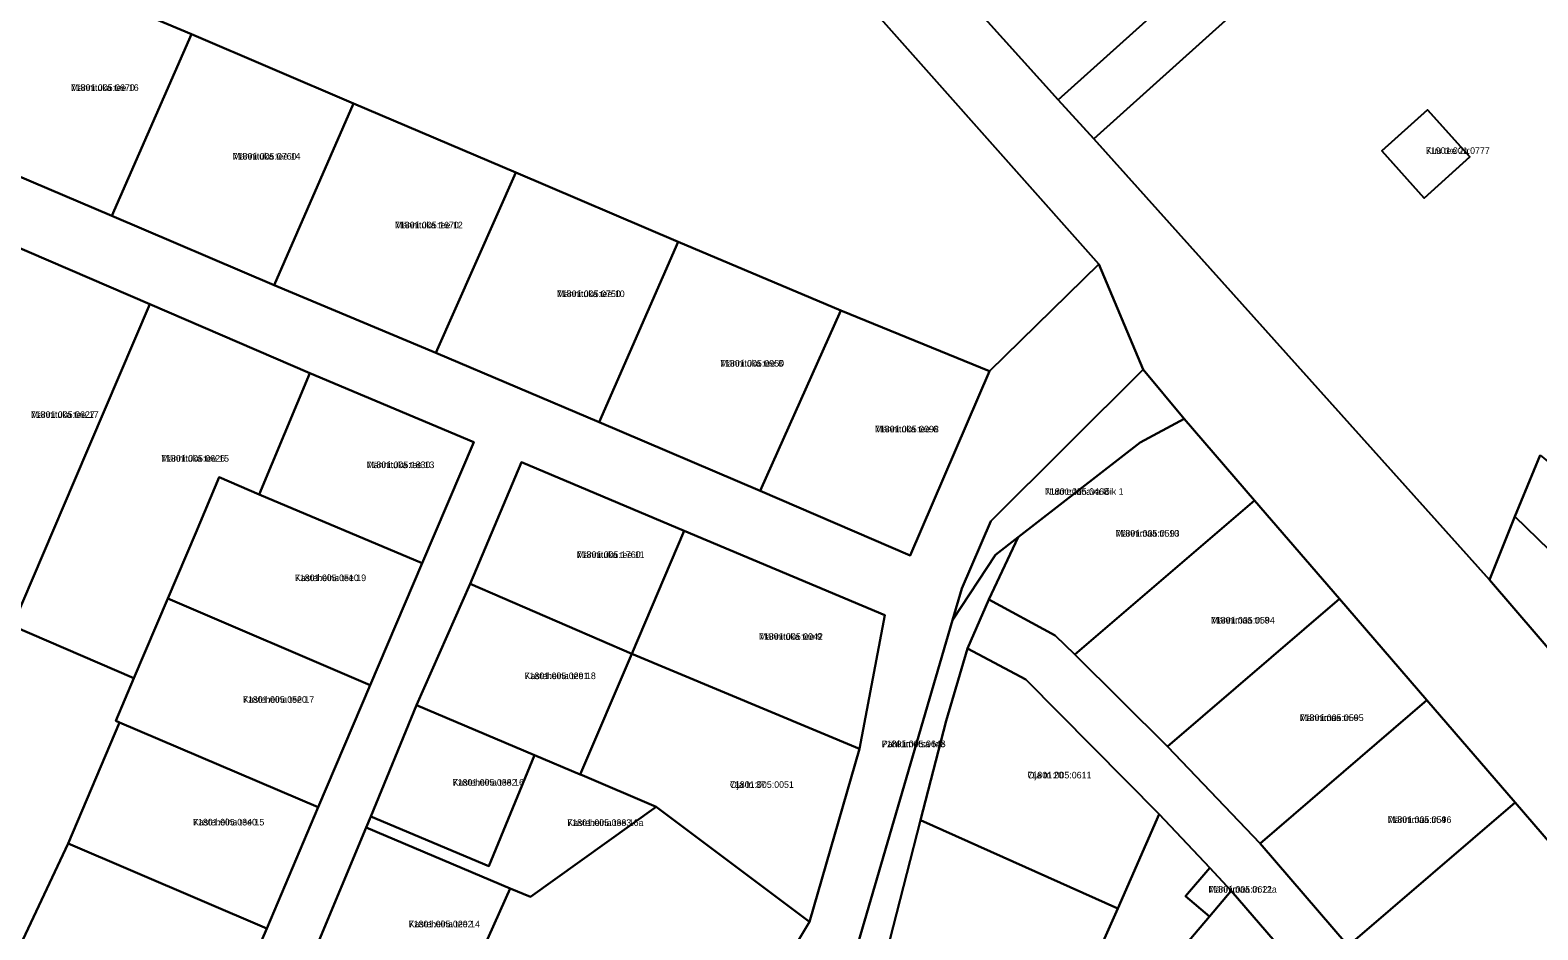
# Model space of a CAD drawing. Extents: x 529768 to 552006, y 6562269 to 6580975.
# Drawn here: x 536849.5 to 537191.7, y 6574356.4 to 6574560.6 of the extents above; entities that cross this region are included whole.
import ezdxf

# ---------------------------------------------------------------- set-up
doc = ezdxf.new("R2010")
doc.units = 0
for name, color, linetype in [('L_AADRESS', 7, 'Continuous'), ('PIIR', 7, 'Continuous'), ('TUNNUS', 7, 'Continuous')]:
    doc.layers.add(name, color=color, linetype=linetype)

msp = doc.modelspace()

# ---------------------------------------------------------------- linework, layer by layer
at = {"layer": 'PIIR'}
for points in [[(536590, 6574730.51), (536689.98, 6574754.28), (536735.05, 6574764.99), (536753.27, 6574769.32), (536801.83, 6574780.81), (536855.94, 6574790.6), (536939.88, 6574703.31), (536970.4, 6574669.45), (537007.93, 6574627.87), (537045.37, 6574586.35), (537082.85, 6574544.79), (537090.91, 6574535.89), (537180.73, 6574435.88), (537224.86, 6574384.41)], [(537192.18, 6574464.15), (537186.43, 6574450.25), (537180.73, 6574435.88), (537090.91, 6574535.89), (537128.25, 6574569.55), (537128.23, 6574583.36), (537176.67, 6574583.41), (537176.67, 6574608.16), (537176.65, 6574632.98), (537176.69, 6574663.91), (537176.66, 6574694.89), (537176.65, 6574725.87), (537176.64, 6574780.86), (537192.46, 6574780.83)], [(537204.91, 6574363.99), (537186.5, 6574385.35), (537166.46, 6574408.59), (537146.64, 6574431.57), (537127.41, 6574453.87), (537111.43, 6574472.43), (537102.12, 6574483.57), (537092.03, 6574507.49), (536928.63, 6574691.42), (536926.96, 6574690.25), (536887.33, 6574717.24), (536796.81, 6574745.22), (536713.32, 6574740.69), (536520.11, 6574695.44)], [(537128.25, 6574569.55), (537090.91, 6574535.89), (537082.85, 6574544.79), (537110.82, 6574569.97)], [(536831.37, 6574534.01), (536868.06, 6574518.43), (536904.91, 6574502.75), (536941.57, 6574487.39), (536978.69, 6574471.64), (537015.22, 6574456.04), (537049.26, 6574441.38), (537067.26, 6574483.19), (537092.03, 6574507.49), (537102.12, 6574483.57), (537067.51, 6574449.2), (537060.96, 6574433.92), (537058.85, 6574426.74), (537037.46, 6574353.46)], [(536848.11, 6574218.76), (536855.09, 6574238.97), (536868.03, 6574273.98), (536879.6, 6574301.9), (536891.37, 6574329.26), (536903.26, 6574356.78), (536914.89, 6574384.31), (536926.66, 6574411.99), (536938.46, 6574439.65), (536950.24, 6574467.12), (536913.03, 6574482.78), (536876.66, 6574498.44), (536839.93, 6574514.2)], [(537000.17, 6574314.62), (537026.37, 6574358.24), (537037.73, 6574397.52), (537043.52, 6574427.85), (536997.92, 6574446.98), (536961, 6574462.58), (536949.35, 6574434.97), (536937.24, 6574407.39), (536926.84, 6574382.16), (536925.81, 6574379.67), (536914.39, 6574352.3)], [(537037.46, 6574353.46), (537058.85, 6574426.74), (537068.61, 6574441.57), (537073.71, 6574445.54), (537067.08, 6574431.41), (537062.23, 6574420.29), (537057.44, 6574403.85), (537051.59, 6574381.3), (537042.29, 6574345.06)], [(537164.41, 6574316.2), (537122.1, 6574365.31), (537117.24, 6574370.49), (537105.74, 6574382.67), (537075.45, 6574413.25), (537062.23, 6574420.29), (537067.08, 6574431.41), (537082.18, 6574423.23), (537086.64, 6574418.89), (537107.65, 6574398.03), (537128.66, 6574376.07), (537148.66, 6574352.81)]]:
    msp.add_lwpolyline(points, dxfattribs=at)
for points in [[(536928.63, 6574691.42), (537092.03, 6574507.49), (537067.26, 6574483.19), (537033.54, 6574496.94), (536996.55, 6574512.59), (536959.71, 6574528.31), (536922.92, 6574543.94), (536886.16, 6574559.68), (536849.27, 6574575.22), (536820.53, 6574587.72), (536818.21, 6574611.88), (536926.96, 6574690.25)], [(537045.37, 6574586.35), (537078.53, 6574616.33), (537115.01, 6574576), (537113.2, 6574572.75), (537110.82, 6574569.97), (537082.85, 6574544.79)], [(536831.37, 6574534.01), (536849.27, 6574575.22), (536886.16, 6574559.68), (536868.06, 6574518.43)], [(536868.06, 6574518.43), (536886.16, 6574559.68), (536922.92, 6574543.94), (536904.91, 6574502.75)], [(536922.92, 6574543.94), (536959.71, 6574528.31), (536941.57, 6574487.39), (536904.91, 6574502.75)], [(537166.61, 6574542.53), (537156.28, 6574533.19), (537165.92, 6574522.49), (537176.26, 6574531.83)], [(537156.28, 6574533.19), (537166.61, 6574542.53), (537176.26, 6574531.83), (537165.92, 6574522.49)], [(536941.57, 6574487.39), (536959.71, 6574528.31), (536996.55, 6574512.59), (536978.69, 6574471.64)], [(536839.93, 6574514.2), (536876.66, 6574498.44), (536859.56, 6574458.37), (536845.49, 6574425.39), (536836.15, 6574449.5), (536833.45, 6574469.67), (536822.7, 6574474.35)], [(536978.69, 6574471.64), (536996.55, 6574512.59), (537033.54, 6574496.94), (537015.22, 6574456.04)], [(536876.66, 6574498.44), (536913.03, 6574482.78), (536901.51, 6574455.21), (536892.44, 6574459.16), (536887.09, 6574446.5), (536880.8, 6574431.62), (536873.08, 6574413.57), (536845.49, 6574425.39), (536859.56, 6574458.37)], [(537033.54, 6574496.94), (537067.26, 6574483.19), (537049.26, 6574441.38), (537015.22, 6574456.04)], [(536938.46, 6574439.65), (536901.51, 6574455.21), (536913.03, 6574482.78), (536950.24, 6574467.12)], [(537102.12, 6574483.57), (537111.43, 6574472.43), (537101.45, 6574466.99), (537073.71, 6574445.54), (537068.61, 6574441.57), (537058.85, 6574426.74), (537060.96, 6574433.92), (537067.51, 6574449.2)], [(537073.71, 6574445.54), (537101.45, 6574466.99), (537111.43, 6574472.43), (537127.41, 6574453.87), (537086.64, 6574418.89), (537082.18, 6574423.23), (537067.08, 6574431.41)], [(536961, 6574462.58), (536997.92, 6574446.98), (536986.06, 6574419.09), (536949.35, 6574434.97)], [(537192.18, 6574464.15), (537220.58, 6574440.85), (537218.46, 6574438.23), (537209.84, 6574427.53), (537186.43, 6574450.25)], [(536880.8, 6574431.62), (536887.09, 6574446.5), (536892.44, 6574459.16), (536901.51, 6574455.21), (536938.46, 6574439.65), (536926.66, 6574411.99)], [(537086.64, 6574418.89), (537127.41, 6574453.87), (537146.64, 6574431.57), (537107.65, 6574398.03)], [(536762.38, 6574420.71), (536836.15, 6574449.5), (536845.49, 6574425.39), (536873.08, 6574413.57), (536868.97, 6574403.9), (536869.83, 6574403.48), (536858.12, 6574376.04), (536845.45, 6574349.03), (536833.59, 6574321.31), (536793.95, 6574337.96), (536798.2, 6574304.12), (536790.31, 6574302.7), (536785.26, 6574343.2), (536774, 6574381.13)], [(537242.33, 6574419.06), (537224.86, 6574384.41), (537180.73, 6574435.88), (537186.43, 6574450.25), (537209.84, 6574427.53), (537218.46, 6574438.23)], [(537043.52, 6574427.85), (537037.73, 6574397.52), (536986.06, 6574419.09), (536997.92, 6574446.98)], [(536949.35, 6574434.97), (536986.06, 6574419.09), (536974.34, 6574391.7), (536963.96, 6574396.08), (536937.24, 6574407.39)], [(536868.97, 6574403.9), (536873.08, 6574413.57), (536880.8, 6574431.62), (536926.66, 6574411.99), (536914.89, 6574384.31), (536869.83, 6574403.48)], [(537107.65, 6574398.03), (537146.64, 6574431.57), (537166.46, 6574408.59), (537128.66, 6574376.07)], [(537062.23, 6574420.29), (537075.45, 6574413.25), (537105.74, 6574382.67), (537096.34, 6574361.32), (537051.59, 6574381.3), (537057.44, 6574403.85)], [(536974.34, 6574391.7), (536986.06, 6574419.09), (537037.73, 6574397.52), (537026.37, 6574358.24), (536991.59, 6574384.37), (536974.8, 6574391.52)], [(536937.24, 6574407.39), (536963.96, 6574396.08), (536953.61, 6574370.9), (536926.84, 6574382.16)], [(537128.66, 6574376.07), (537166.46, 6574408.59), (537186.5, 6574385.35), (537148.66, 6574352.81)], [(536858.12, 6574376.04), (536869.83, 6574403.48), (536914.89, 6574384.31), (536903.26, 6574356.78)], [(536963.96, 6574396.08), (536974.34, 6574391.7), (536974.8, 6574391.52), (536991.59, 6574384.37), (536963.07, 6574363.94), (536958.43, 6574365.86), (536925.81, 6574379.67), (536926.84, 6574382.16), (536953.61, 6574370.9)], [(537026.37, 6574358.24), (537000.17, 6574314.62), (536960.21, 6574332.56), (536955.96, 6574334.35), (536962, 6574347.99), (536952.35, 6574352.12), (536958.43, 6574365.86), (536963.07, 6574363.94), (536991.59, 6574384.37)], [(537105.74, 6574382.67), (537117.24, 6574370.49), (537111.74, 6574364.05), (537117.15, 6574359.47), (537101.43, 6574340.92), (537084.21, 6574320.56), (537079.92, 6574324.18), (537081.47, 6574327.75), (537096.34, 6574361.32)], [(537148.66, 6574352.81), (537186.5, 6574385.35), (537204.91, 6574363.99), (537177.64, 6574331.83), (537172.56, 6574329.53), (537167.43, 6574331.07)], [(536925.81, 6574379.67), (536958.43, 6574365.86), (536952.35, 6574352.12), (536962, 6574347.99), (536955.96, 6574334.35), (536914.39, 6574352.3)], [(537051.59, 6574381.3), (537096.34, 6574361.32), (537081.47, 6574327.75), (537042.29, 6574345.06)], [(536903.26, 6574356.78), (536891.37, 6574329.26), (536845.45, 6574349.03), (536858.12, 6574376.04)], [(537117.24, 6574370.49), (537122.1, 6574365.31), (537117.15, 6574359.47), (537111.74, 6574364.05)], [(537122.1, 6574365.31), (537164.41, 6574316.2), (537150.3, 6574299.57), (537101.43, 6574340.92), (537117.15, 6574359.47)]]:
    msp.add_lwpolyline(points, close=True, dxfattribs=at)

# ---------------------------------------------------------------- texts
at = {"layer": 'L_AADRESS'}
for s, p in [('Männituka tee 16', (536858.76, 6574546.8)), ('Männituka tee 14', (536895.49, 6574531.22)), ('Kuu tee 2a', (537166.27, 6574532.51)), ('Männituka tee 12', (536932.31, 6574515.61)), ('Männituka tee 10', (536969.06, 6574500.02)), ('Männituka tee 8', (537006.11, 6574484.24)), ('Männituka tee 17', (536849.68, 6574472.61)), ('Männituka tee 6', (537041.24, 6574469.32)), ('Männituka tee 15', (536879.26, 6574462.67)), ('Männituka tee 13', (536925.86, 6574461.21)), ('Nurme tänava lõik 1', (537079.83, 6574455.15)), ('Männimaa tn 10', (537095.85, 6574445.66)), ('Männituka tee 11', (536973.57, 6574440.83)), ('Kasteheina tee 19', (536909.6, 6574435.57)), ('Männimaa tn 8', (537117.49, 6574425.95)), ('Männituka tee 9', (537014.93, 6574422.25)), ('Kasteheina tee 18', (536961.72, 6574413.33)), ('Kasteheina tee 17', (536897.82, 6574407.96)), ('Männimaa tn 6', (537137.65, 6574403.82)), ('Pähklimetsa tee', (537042.79, 6574397.89)), ('Kasteheina tee 16', (536945.41, 6574389.15)), ('Oja tn 37', (537008.34, 6574388.66)), ('Oja tn 20', (537075.87, 6574390.8)), ('Männimaa tn 4', (537157.57, 6574380.7)), ('Kasteheina tee 15', (536886.49, 6574380.13)), ('Kasteheina tee 16a', (536971.43, 6574380.01)), ('Männimaa tn 12a', (537116.92, 6574364.89)), ('Kasteheina tee 14', (536935.43, 6574357.01))]:
    msp.add_text(s, height=1.5, dxfattribs=at).set_placement(p)
at = {"layer": 'TUNNUS'}
for s, p in [('71801:005:0670', (536858.76, 6574546.8)), ('71901:001:0777', (537166.27, 6574532.51)), ('71801:005:0760', (536895.49, 6574531.22)), ('71801:005:1670', (536932.31, 6574515.61)), ('71801:005:0750', (536969.06, 6574500.02)), ('71801:005:0950', (537006.11, 6574484.24)), ('71801:005:0627', (536849.68, 6574472.61)), ('71801:005:0098', (537041.24, 6574469.32)), ('71801:005:0626', (536879.26, 6574462.67)), ('71801:005:1830', (536925.86, 6574461.21)), ('71801:005:0468', (537079.83, 6574455.15)), ('71801:005:0593', (537095.85, 6574445.66)), ('71801:005:1760', (536973.57, 6574440.83)), ('71801:005:0510', (536909.6, 6574435.57)), ('71801:005:0594', (537117.49, 6574425.95)), ('71801:005:0042', (537014.93, 6574422.25)), ('71801:005:0291', (536961.72, 6574413.33)), ('71801:005:0520', (536897.82, 6574407.96)), ('71801:005:0595', (537137.65, 6574403.82)), ('71801:005:0648', (537042.79, 6574397.89)), ('71801:005:0382', (536945.41, 6574389.15)), ('71801:005:0051', (537008.34, 6574388.66)), ('71801:005:0611', (537075.87, 6574390.8)), ('71801:005:0596', (537157.57, 6574380.7)), ('71801:005:0340', (536886.49, 6574380.13)), ('71801:005:0383', (536971.43, 6574380.01)), ('71801:005:0621', (537116.92, 6574364.89)), ('71801:005:0292', (536935.43, 6574357.01))]:
    msp.add_text(s, height=1.5, dxfattribs=at).set_placement(p)

doc.saveas('drawing.dxf')
